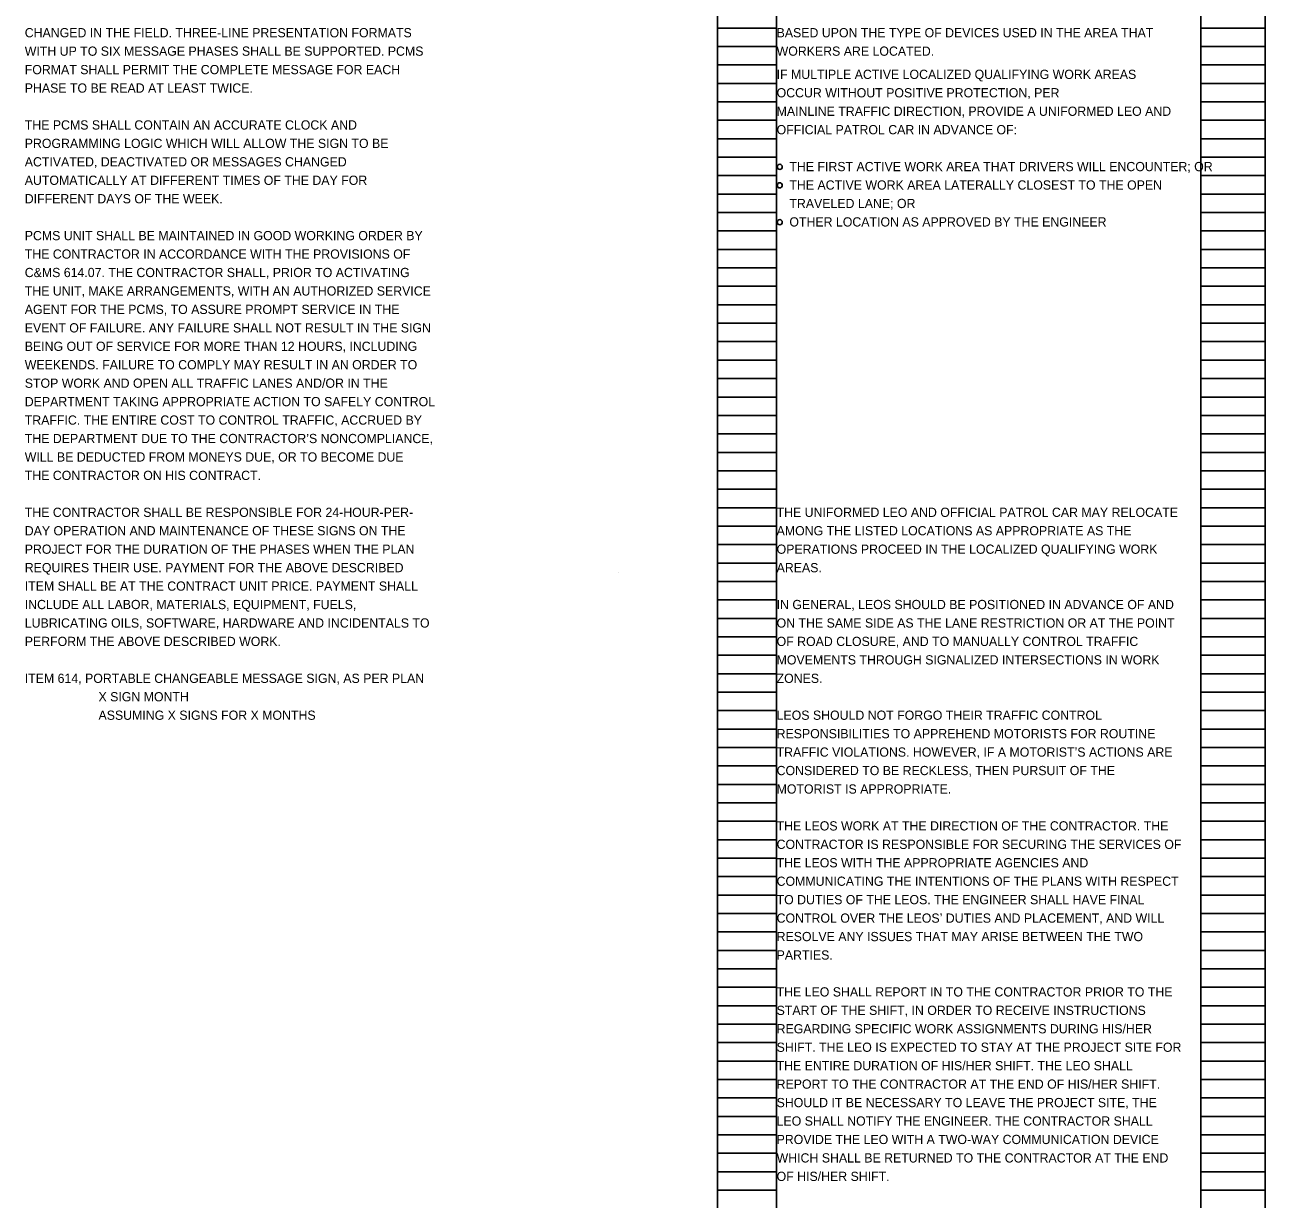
# Model space of a CAD drawing. Extents: x -9 to 32, y -122 to 20.
# Drawn here: x -9.3 to 9.54, y -50.51 to -32.68 of the extents above; entities that cross this region are included whole.
import ezdxf

# ---------------------------------------------------------------- set-up
doc = ezdxf.new("R2010")
doc.units = 0
doc.layers.add('SC_Scratch1', color=7, linetype='Continuous')
doc.layers.add('SH_Text', color=7, linetype='Continuous')

msp = doc.modelspace()

# ---------------------------------------------------------------- linework, layer by layer
at = {"layer": 'SC_Scratch1'}
for p, q in [((1.216, -40.014), (1.216, -19.854)), ((2.116, -40.014), (2.116, -19.854)), ((8.556, -40.014), (8.556, -19.854)), ((9.536, -40.014), (9.536, -19.854)), ((1.216, -32.734), (2.116, -32.734)), ((8.556, -32.734), (9.536, -32.734)), ((1.216, -33.014), (2.116, -33.014)), ((8.556, -33.014), (9.536, -33.014)), ((1.216, -33.294), (2.116, -33.294)), ((8.556, -33.294), (9.536, -33.294)), ((1.216, -33.574), (2.116, -33.574)), ((8.556, -33.574), (9.536, -33.574)), ((1.216, -33.854), (2.116, -33.854)), ((8.556, -33.854), (9.536, -33.854)), ((1.216, -34.134), (2.116, -34.134)), ((8.556, -34.134), (9.536, -34.134)), ((1.216, -34.414), (2.116, -34.414)), ((8.556, -34.414), (9.536, -34.414)), ((1.216, -34.694), (2.116, -34.694)), ((8.556, -34.694), (9.536, -34.694)), ((1.216, -34.974), (2.116, -34.974)), ((8.556, -34.974), (9.536, -34.974)), ((1.216, -35.254), (2.116, -35.254)), ((8.556, -35.254), (9.536, -35.254)), ((1.216, -35.534), (2.116, -35.534)), ((8.556, -35.534), (9.536, -35.534)), ((1.216, -35.814), (2.116, -35.814)), ((8.556, -35.814), (9.536, -35.814)), ((1.216, -36.094), (2.116, -36.094)), ((8.556, -36.094), (9.536, -36.094)), ((1.216, -36.374), (2.116, -36.374)), ((8.556, -36.374), (9.536, -36.374)), ((1.216, -36.654), (2.116, -36.654)), ((8.556, -36.654), (9.536, -36.654)), ((1.216, -36.934), (2.116, -36.934)), ((8.556, -36.934), (9.536, -36.934)), ((1.216, -37.214), (2.116, -37.214)), ((8.556, -37.214), (9.536, -37.214)), ((1.216, -37.494), (2.116, -37.494)), ((8.556, -37.494), (9.536, -37.494)), ((1.216, -37.774), (2.116, -37.774)), ((8.556, -37.774), (9.536, -37.774)), ((1.216, -38.054), (2.116, -38.054)), ((8.556, -38.054), (9.536, -38.054)), ((1.216, -38.334), (2.116, -38.334)), ((8.556, -38.334), (9.536, -38.334)), ((1.216, -38.614), (2.116, -38.614)), ((8.556, -38.614), (9.536, -38.614)), ((1.216, -38.894), (2.116, -38.894)), ((8.556, -38.894), (9.536, -38.894)), ((1.216, -39.174), (2.116, -39.174)), ((8.556, -39.174), (9.536, -39.174)), ((1.216, -39.454), (2.116, -39.454)), ((8.556, -39.454), (9.536, -39.454)), ((1.216, -39.734), (2.116, -39.734)), ((8.556, -39.734), (9.536, -39.734)), ((1.216, -40.014), (2.116, -40.014)), ((1.216, -60.174), (1.216, -40.014)), ((1.216, -40.014), (2.116, -40.014)), ((2.116, -60.174), (2.116, -40.014)), ((8.556, -40.014), (9.536, -40.014)), ((8.556, -60.174), (8.556, -40.014)), ((8.556, -40.014), (9.536, -40.014)), ((9.536, -60.174), (9.536, -40.014)), ((1.216, -40.294), (2.116, -40.294)), ((8.556, -40.294), (9.536, -40.294)), ((1.216, -40.574), (2.116, -40.574)), ((8.556, -40.574), (9.536, -40.574)), ((1.216, -40.854), (2.116, -40.854)), ((8.556, -40.854), (9.536, -40.854)), ((-0.284, -40.994), (-0.284, -40.994)), ((1.216, -41.134), (2.116, -41.134)), ((8.556, -41.134), (9.536, -41.134)), ((1.216, -41.414), (2.116, -41.414)), ((8.556, -41.414), (9.536, -41.414)), ((1.216, -41.694), (2.116, -41.694)), ((8.556, -41.694), (9.536, -41.694)), ((1.216, -41.974), (2.116, -41.974)), ((8.556, -41.974), (9.536, -41.974)), ((1.216, -42.254), (2.116, -42.254)), ((8.556, -42.254), (9.536, -42.254)), ((1.216, -42.534), (2.116, -42.534)), ((8.556, -42.534), (9.536, -42.534)), ((1.216, -42.814), (2.116, -42.814)), ((8.556, -42.814), (9.536, -42.814)), ((1.216, -43.094), (2.116, -43.094)), ((8.556, -43.094), (9.536, -43.094)), ((1.216, -43.374), (2.116, -43.374)), ((8.556, -43.374), (9.536, -43.374)), ((1.216, -43.654), (2.116, -43.654)), ((8.556, -43.654), (9.536, -43.654)), ((1.216, -43.934), (2.116, -43.934)), ((8.556, -43.934), (9.536, -43.934)), ((1.216, -44.214), (2.116, -44.214)), ((8.556, -44.214), (9.536, -44.214)), ((1.216, -44.494), (2.116, -44.494)), ((8.556, -44.494), (9.536, -44.494)), ((1.216, -44.774), (2.116, -44.774)), ((8.556, -44.774), (9.536, -44.774)), ((1.216, -45.054), (2.116, -45.054)), ((8.556, -45.054), (9.536, -45.054)), ((1.216, -45.334), (2.116, -45.334)), ((8.556, -45.334), (9.536, -45.334)), ((1.216, -45.614), (2.116, -45.614)), ((8.556, -45.614), (9.536, -45.614)), ((1.216, -45.894), (2.116, -45.894)), ((8.556, -45.894), (9.536, -45.894)), ((1.216, -46.174), (2.116, -46.174)), ((8.556, -46.174), (9.536, -46.174)), ((1.216, -46.454), (2.116, -46.454)), ((8.556, -46.454), (9.536, -46.454)), ((1.216, -46.734), (2.116, -46.734)), ((8.556, -46.734), (9.536, -46.734)), ((1.216, -47.014), (2.116, -47.014)), ((8.556, -47.014), (9.536, -47.014)), ((1.216, -47.294), (2.116, -47.294)), ((8.556, -47.294), (9.536, -47.294)), ((1.216, -47.574), (2.116, -47.574)), ((8.556, -47.574), (9.536, -47.574)), ((1.216, -47.854), (2.116, -47.854)), ((8.556, -47.854), (9.536, -47.854)), ((1.216, -48.134), (2.116, -48.134)), ((8.556, -48.134), (9.536, -48.134)), ((1.216, -48.414), (2.116, -48.414)), ((8.556, -48.414), (9.536, -48.414)), ((1.216, -48.694), (2.116, -48.694)), ((8.556, -48.694), (9.536, -48.694)), ((1.216, -48.974), (2.116, -48.974)), ((8.556, -48.974), (9.536, -48.974)), ((1.216, -49.254), (2.116, -49.254)), ((8.556, -49.254), (9.536, -49.254)), ((1.216, -49.534), (2.116, -49.534)), ((8.556, -49.534), (9.536, -49.534)), ((1.216, -49.814), (2.116, -49.814)), ((8.556, -49.814), (9.536, -49.814)), ((1.216, -50.094), (2.116, -50.094)), ((8.556, -50.094), (9.536, -50.094)), ((1.216, -50.374), (2.116, -50.374)), ((8.556, -50.374), (9.536, -50.374))]:
    msp.add_line(p, q, dxfattribs=at)
at = {"layer": 'SH_Text'}
for centre in [(2.163, -34.841), (2.163, -35.121), (2.163, -35.681)]:
    msp.add_circle(centre, 0.0389, dxfattribs=at)

# ---------------------------------------------------------------- texts
for s, p in [('CHANGED IN THE FIELD. THREE-LINE PRESENTATION FORMATS ', (-9.302, -32.874)), ('BASED UPON THE TYPE OF DEVICES USED IN THE AREA THAT ', (2.116, -32.874)), ('WITH UP TO SIX MESSAGE PHASES SHALL BE SUPPORTED. PCMS ', (-9.302, -33.154)), ('WORKERS ARE LOCATED.', (2.116, -33.154)), ('FORMAT SHALL PERMIT THE COMPLETE MESSAGE FOR EACH ', (-9.302, -33.434)), ('IF MULTIPLE ACTIVE LOCALIZED QUALIFYING WORK AREAS ', (2.116, -33.506)), ('PHASE TO BE READ AT LEAST TWICE.', (-9.302, -33.714)), ('OCCUR WITHOUT POSITIVE PROTECTION, PER', (2.116, -33.786)), ('MAINLINE TRAFFIC DIRECTION, PROVIDE A UNIFORMED LEO AND ', (2.116, -34.066)), ('THE PCMS SHALL CONTAIN AN ACCURATE CLOCK AND ', (-9.302, -34.274)), ('OFFICIAL PATROL CAR IN ADVANCE OF:', (2.116, -34.346)), ('PROGRAMMING LOGIC WHICH WILL ALLOW THE SIGN TO BE ', (-9.302, -34.554)), ('ACTIVATED, DEACTIVATED OR MESSAGES CHANGED ', (-9.302, -34.834)), ('THE FIRST ACTIVE WORK AREA THAT DRIVERS WILL ENCOUNTER; OR', (2.31, -34.906)), ('AUTOMATICALLY AT DIFFERENT TIMES OF THE DAY FOR ', (-9.302, -35.114)), ('THE ACTIVE WORK AREA LATERALLY CLOSEST TO THE OPEN ', (2.31, -35.186)), ('DIFFERENT DAYS OF THE WEEK.', (-9.302, -35.394)), ('TRAVELED LANE; OR', (2.31, -35.466)), ('OTHER LOCATION AS APPROVED BY THE ENGINEER', (2.31, -35.746)), ('PCMS UNIT SHALL BE MAINTAINED IN GOOD WORKING ORDER BY ', (-9.302, -35.954)), ('THE CONTRACTOR IN ACCORDANCE WITH THE PROVISIONS OF ', (-9.302, -36.234)), ('C&MS 614.07. THE CONTRACTOR SHALL, PRIOR TO ACTIVATING ', (-9.302, -36.514)), ('THE UNIT, MAKE ARRANGEMENTS, WITH AN AUTHORIZED SERVICE ', (-9.302, -36.794)), ('AGENT FOR THE PCMS, TO ASSURE PROMPT SERVICE IN THE', (-9.302, -37.074)), ('EVENT OF FAILURE. ANY FAILURE SHALL NOT RESULT IN THE SIGN ', (-9.302, -37.354)), ('BEING OUT OF SERVICE FOR MORE THAN 12 HOURS, INCLUDING ', (-9.302, -37.634)), ('WEEKENDS. FAILURE TO COMPLY MAY RESULT IN AN ORDER TO ', (-9.302, -37.914)), ('STOP WORK AND OPEN ALL TRAFFIC LANES AND/OR IN THE ', (-9.302, -38.194)), ('DEPARTMENT TAKING APPROPRIATE ACTION TO SAFELY CONTROL ', (-9.302, -38.474)), ('TRAFFIC. THE ENTIRE COST TO CONTROL TRAFFIC, ACCRUED BY ', (-9.302, -38.754)), ('THE DEPARTMENT DUE TO THE CONTRACTOR’S NONCOMPLIANCE, ', (-9.302, -39.034)), ('WILL BE DEDUCTED FROM MONEYS DUE, OR TO BECOME DUE ', (-9.302, -39.314)), ('THE CONTRACTOR ON HIS CONTRACT.', (-9.302, -39.594)), ('THE CONTRACTOR SHALL BE RESPONSIBLE FOR 24-HOUR-PER-', (-9.302, -40.154)), ('THE UNIFORMED LEO AND OFFICIAL PATROL CAR MAY RELOCATE ', (2.116, -40.154)), ('DAY OPERATION AND MAINTENANCE OF THESE SIGNS ON THE ', (-9.302, -40.434)), ('AMONG THE LISTED LOCATIONS AS APPROPRIATE AS THE ', (2.116, -40.434)), ('PROJECT FOR THE DURATION OF THE PHASES WHEN THE PLAN ', (-9.302, -40.714)), ('OPERATIONS PROCEED IN THE LOCALIZED QUALIFYING WORK ', (2.116, -40.714)), ('REQUIRES THEIR USE. PAYMENT FOR THE ABOVE DESCRIBED ', (-9.302, -40.994)), ('AREAS.', (2.116, -40.994)), ('ITEM SHALL BE AT THE CONTRACT UNIT PRICE. PAYMENT SHALL ', (-9.302, -41.274)), ('INCLUDE ALL LABOR, MATERIALS, EQUIPMENT, FUELS, ', (-9.302, -41.554)), ('IN GENERAL, LEOS SHOULD BE POSITIONED IN ADVANCE OF AND ', (2.116, -41.554)), ('LUBRICATING OILS, SOFTWARE, HARDWARE AND INCIDENTALS TO ', (-9.302, -41.834)), ('ON THE SAME SIDE AS THE LANE RESTRICTION OR AT THE POINT ', (2.116, -41.834)), ('PERFORM THE ABOVE DESCRIBED WORK.', (-9.302, -42.114)), ('OF ROAD CLOSURE, AND TO MANUALLY CONTROL TRAFFIC ', (2.116, -42.114)), ('MOVEMENTS THROUGH SIGNALIZED INTERSECTIONS IN WORK ', (2.116, -42.394)), ('ITEM 614, PORTABLE CHANGEABLE MESSAGE SIGN, AS PER PLAN', (-9.302, -42.674)), ('ZONES.', (2.116, -42.674)), ('X SIGN MONTH', (-8.182, -42.954)), ('ASSUMING X SIGNS FOR X MONTHS', (-8.182, -43.234)), ('LEOS SHOULD NOT FORGO THEIR TRAFFIC CONTROL ', (2.116, -43.234)), ('RESPONSIBILITIES TO APPREHEND MOTORISTS FOR ROUTINE ', (2.116, -43.514)), ('TRAFFIC VIOLATIONS. HOWEVER, IF A MOTORIST’S ACTIONS ARE ', (2.116, -43.794)), ('CONSIDERED TO BE RECKLESS, THEN PURSUIT OF THE ', (2.116, -44.074)), ('MOTORIST IS APPROPRIATE.', (2.116, -44.354)), ('THE LEOS WORK AT THE DIRECTION OF THE CONTRACTOR. THE ', (2.116, -44.914)), ('CONTRACTOR IS RESPONSIBLE FOR SECURING THE SERVICES OF ', (2.116, -45.194)), ('THE LEOS WITH THE APPROPRIATE AGENCIES AND ', (2.116, -45.474)), ('COMMUNICATING THE INTENTIONS OF THE PLANS WITH RESPECT ', (2.116, -45.754)), ('TO DUTIES OF THE LEOS. THE ENGINEER SHALL HAVE FINAL ', (2.116, -46.034)), ('CONTROL OVER THE LEOS’ DUTIES AND PLACEMENT, AND WILL ', (2.116, -46.314)), ('RESOLVE ANY ISSUES THAT MAY ARISE BETWEEN THE TWO ', (2.116, -46.594)), ('PARTIES.', (2.116, -46.874)), ('THE LEO SHALL REPORT IN TO THE CONTRACTOR PRIOR TO THE ', (2.116, -47.434)), ('START OF THE SHIFT, IN ORDER TO RECEIVE INSTRUCTIONS ', (2.116, -47.714)), ('REGARDING SPECIFIC WORK ASSIGNMENTS DURING HIS/HER ', (2.116, -47.994)), ('SHIFT. THE LEO IS EXPECTED TO STAY AT THE PROJECT SITE FOR ', (2.116, -48.274)), ('THE ENTIRE DURATION OF HIS/HER SHIFT. THE LEO SHALL ', (2.116, -48.554)), ('REPORT TO THE CONTRACTOR AT THE END OF HIS/HER SHIFT. ', (2.116, -48.834)), ('SHOULD IT BE NECESSARY TO LEAVE THE PROJECT SITE, THE ', (2.116, -49.114)), ('LEO SHALL NOTIFY THE ENGINEER. THE CONTRACTOR SHALL ', (2.116, -49.394)), ('PROVIDE THE LEO WITH A TWO-WAY COMMUNICATION DEVICE ', (2.116, -49.674)), ('WHICH SHALL BE RETURNED TO THE CONTRACTOR AT THE END ', (2.116, -49.954)), ('OF HIS/HER SHIFT.', (2.116, -50.234))]:
    msp.add_text(s, height=0.14, dxfattribs=at).set_placement(p)

doc.saveas('drawing.dxf')
